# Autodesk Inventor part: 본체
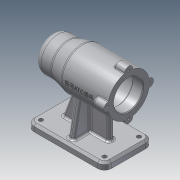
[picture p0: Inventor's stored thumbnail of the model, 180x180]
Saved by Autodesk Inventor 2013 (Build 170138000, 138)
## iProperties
Created: 2019-07
Part Number: 본체
Material: 알루미늄 6061
Document SubType Name: Modeling
Designer: 12
Density: 2.71 g/cm^3
Mass: 646.085 g
Surface Area: 655.731 cm^2
Volume: 238.408 cm^3
Author: 12
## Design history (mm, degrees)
sketch "스케치1"
  geometry: L1 (-56, 0)-(56, 0); L2 (-56, 0)-(-56, 25); L3 (-56, 25)-(-31, 25); L4 (-31, 25)-(-11, 30); L5 (-11, 30)-(56, 30); L6 (56, 30)-(56, 0); 2 further points
  constraints: 12 end point, 2 parallel, 2 perpendicular, 1 coincident, 1 horizontal, 1 midpoint
  dimensions: "d0" = 112 distance of L1.start L1.end; "d1" = 60 diameter of L5 L1; "d2" = 50 diameter of L3 L1; "d3" = 45 distance from line of L4.end L2; "d4" = 25 distance of L2.end L3.end
revolve "회전1" sketch "스케치1" stored, may be unused: angle "d5" = 90 deg
sketch "스케치2"
  geometry: C1 r 30 at (0, 0) reference; C2 r 21 at (0, 0)
  constraints: 1 centre point, 1 coincident
  dimensions: "d6" = 42 diameter of C2
extrude "돌출1" cut sketch "스케치2" distance "d7" = 15; taper "d8" = 0 deg
sketch "스케치3"
  geometry: C1 r 21 at (0, 0) reference; C2 r 24 at (0, 0)
  constraints: 1 centre point, 1 coincident
  dimensions: "d9" = 48 diameter of C2
extrude "돌출2" cut sketch "스케치3" distance "d10" = 54; taper "d11" = 0 deg
sketch "스케치4"
  geometry: C1 r 24 at (0, 0) reference; C2 r 21 at (0, 0)
  constraints: 1 centre point, 1 coincident
  dimensions: "d12" = 42 diameter of C2
extrude "돌출3" cut sketch "스케치4" distance "d13" = 12; taper "d14" = 0 deg
sketch "스케치5"
  geometry: C1 r 21 at (0, 0) reference; C2 r 17.5 at (0, 0)
  constraints: 1 centre point, 1 coincident
  dimensions: "d15" = 35 diameter of C2
extrude "돌출4" cut sketch "스케치5" distance "d16" = 18; taper "d17" = 0 deg
sketch "스케치6"
  geometry: C1 r 17.5 at (0, 0) reference; C2 r 16 at (0, 0)
  constraints: 1 centre point, 1 coincident
  dimensions: "d18" = 32 diameter of C2
extrude "돌출5" cut sketch "스케치6" distance "d19" = 4; taper "d20" = 0 deg
sketch "스케치8"
  geometry: L1 (0, 0)-(0, 30); C1 r 30 at (0, 0) reference; C2 r 6 at (0, 30)
  constraints: 2 end point, 1 centre point, 1 coincident, 1 vertical
  dimensions: "d26" = 30 distance of L1.start L1.end; "d27" = 12 diameter of C2
extrude "돌출6" join sketch "스케치8" distance "d28" = 16; taper "d29" = 0 deg
sketch "스케치9"
  geometry: A1 r 6 centre (0, 0) between (5.97, -0.6) and (-5.97, -0.6) reference; A2 r 6 centre (-30, -30) between (-29.4, -24.03) and (-29.4, -35.97) reference; A3 r 6 centre (0, -60) between (-5.97, -59.4) and (5.97, -59.4) reference; A4 r 6 centre (30, -30) between (29.4, -35.97) and (29.4, -24.03) reference; 4 further points
  constraints: 4 coincident
hole "구멍1" sketch "스케치9" at (0, 0), (30, -30), (-30, -30), (0, -60) diameter "d33" = 3.242; stored, may be unused: countersink angle "d37" = 90 deg, drill point angle "d39" = 118 deg; dims "d34" = 8, "d35" = 4, "d36" = 2, "d38" = 11
sketch "스케치10"
  geometry: C1 r 16 at (0, 0) reference; C2 r 10.5 at (0, 0)
  constraints: 1 centre point, 1 coincident
  dimensions: "d41" = 21 diameter of C2
extrude "돌출7" cut sketch "스케치10" distance "d42" = 3; taper "d43" = 0 deg
node "작업 평면1"
sketch "스케치11"
  geometry: L1 (56, 35)-(-56, 35); L2 (-56, 35)-(-56, -35); L3 (-56, -35)-(56, -35); L4 (56, -35)-(56, 35); L5 (56, 5.97)-(56, 29.4) reference; L6 (56, 6)-(56, -6) reference; L7 (56, -29.4)-(56, -5.97) reference; L8 (56, -29.4)-(56, -36) reference; L9 (56, 36)-(56, 29.4) reference; 2 further points
  constraints: 8 end point, 2 midpoint, 2 parallel, 1 horizontal, 1 perpendicular
  dimensions: "d45" = 112 distance of L3.end L2.end; "d46" = 70 distance of L2.end L1.end
extrude "돌출8" join sketch "스케치11" distance "d47" = 10; taper "d48" = 0 deg
fillet "모깎기1" dims "d60" = 10
sketch "스케치14"
  geometry: A1 r 10 centre (-46, 25) between (-46, 35) and (-56, 25) reference; A2 r 10 centre (-46, -25) between (-56, -25) and (-46, -35) reference; A3 r 10 centre (46, -25) between (46, -35) and (56, -25) reference; A4 r 10 centre (46, 25) between (56, 25) and (46, 35) reference; 5 further points
  constraints: 4 coincident
hole "구멍2" sketch "스케치14" at (-46, 25), (46, 25), (-46, -25), (46, -25) diameter "d61" = 6; stored, may be unused: countersink angle "d65" = 90 deg, drill point angle "d67" = 118 deg; dims "d62" = 8, "d63" = 4, "d64" = 2, "d66" = 11
fillet "모깎기2" dims "d68" = 10
fillet "모깎기3" dims "d69" = 0.3
fillet "모깎기4" dims "d70" = 3
fillet "모깎기5" dims "d71" = 3
chamfer "모따기1" distance "d72" = 1; stored, may be unused: second distance "d73" = 2, angle "d74" = 45 deg
chamfer "모따기2" distance "d75" = 3; stored, may be unused: second distance "d76" = 2, angle "d77" = 45 deg
sketch "스케치20"
  geometry: L1 (3, 4)-(31, 4); L2 (31, 4)-(31, -4); L3 (31, -4)-(3, -4); L4 (3, -4)-(3, 4); L5 (56, -25)-(56, 25) reference; L6 (46, -32)-(-46, -32) reference; L7 (46, 35)-(-46, 35) reference; L8 (-46, -35)-(46, -35) reference; 1 further point
  constraints: 8 end point, 2 parallel, 1 horizontal, 1 perpendicular
  dimensions: "d103" = 25 distance between parallel lines of L5 L2; "d119" = 28 distance of L1.start L1.end; "d120" = 31 distance between parallel lines of L7 L1; "d121" = 28 distance between parallel lines of L6 L3
extrude "돌출12" join sketch "스케치20" stored distance "d104" = 8; taper "d105" = 0 deg
fillet "모깎기6" dims "d78" = 3
fillet "모깎기7" dims "d79" = 3
fillet "모깎기8" dims "d80" = 1
node "작업 평면2"
sketch "스케치16"
  geometry: L1 (56, 6.771)-(56, 29.226) reference; L2 (56, 36)-(56, 30.171) reference; 2 further points
  constraints: 1 horizontal alignment, 1 other
  dimensions: "d85" = 42 distance from line of L2 point (14, 0)
feature "엠보싱1" sketch "스케치16" dims "d0" = 112, "d1" = 60, "d2" = 50, "d3" = 45, "d4" = 25, "d10" = 54, "d86" = 0.5, "d87" = 0
sketch "스케치17"
  geometry: L1 (45, -28.379)-(44.026, -30) reference; L2 (44.026, -30)-(45, -31.621) reference; L3 (45, -31.621)-(56, -31.621) reference; L4 (56, -31.621)-(56, -36) reference; L5 (56, -36)-(43, -36) reference; L6 (40, -33)-(40, -31) reference; L7 (39, -30)-(31, -30) reference; L8 (31, -70)-(53, -70) reference; L9 (53, -70)-(56, -73) reference; L10 (56, -73)-(56, -80) reference; L11 (56, -80)-(-56, -80) reference; L12 (-56, -80)-(-56, -73) reference; L13 (-56, -73)-(-53, -70) reference; L14 (-53, -70)-(3, -70) reference; L15 (3, -30)-(-11, -30) reference; L16 (-11, -30)-(-31, -25) reference; L17 (-31, -25)-(-46, -25) reference; L18 (-56, -15)-(-56, 15) reference; L19 (-46, 25)-(-31, 25) reference; L20 (-31, 25)-(-11, 30) reference; L21 (-11, 30)-(39, 30) reference; L22 (40, 31)-(40, 33) reference; L23 (43, 36)-(56, 36) reference; L24 (56, 36)-(56, 31.621) reference; L25 (56, 31.621)-(45, 31.621) reference; L26 (45, 31.621)-(44.026, 30) reference; L27 (44.026, 30)-(45, 28.379) reference; L28 (45, 28.379)-(56, 28.379) reference; L29 (56, 28.379)-(56, 22) reference; L30 (56, 22)-(55, 21) reference; L31 (55, 21)-(41, 21) reference; L32 (38, 24)-(-10, 24) reference; L33 (-13, 21)-(-24.7, 21) reference; L34 (-25, 20.7)-(-25, 17.5) reference; L35 (-25, 17.5)-(-42.7, 17.5) reference; L36 (-43, 17.2)-(-43, 16) reference; L37 (-43, 16)-(-46.7, 16) reference; L38 (-47, 15.7)-(-47, 10.5) reference; L39 (-50, 7.5)-(-50, -7.5) reference; L40 (-47, -10.5)-(-47, -15.7) reference; L41 (-46.7, -16)-(-43, -16) reference; L42 (-43, -16)-(-43, -17.2) reference; L43 (-42.7, -17.5)-(-25, -17.5) reference; L44 (-25, -17.5)-(-25, -20.7) reference; L45 (-24.7, -21)-(-13, -21) reference; L46 (-10, -24)-(38, -24) reference; L47 (41, -21)-(55, -21) reference; L48 (55, -21)-(56, -22) reference; L49 (56, -22)-(56, -28.379) reference; L50 (56, -28.379)-(45, -28.379) reference; L51 (-20.57, -27.607)-(-36, -70); L52 (31, -30)-(31, -70) reference; L53 (3, -70)-(3, -30) reference; A1 r 3 centre (43, -33) between (40, -33) and (43, -36) reference; A2 r 1 centre (39, -31) between (40, -31) and (39, -30) reference; A3 r 10 centre (-46, -15) between (-56, -15) and (-46, -25) reference; A4 r 10 centre (-46, 15) between (-46, 25) and (-56, 15) reference; A5 r 1 centre (39, 31) between (39, 30) and (40, 31) reference; A6 r 3 centre (43, 33) between (43, 36) and (40, 33) reference; A7 r 3 centre (38, 21) between (41, 21) and (38, 24) reference; A8 r 3 centre (-10, 21) between (-10, 24) and (-13, 21) reference; A9 r 0.3 centre (-24.7, 20.7) between (-24.7, 21) and (-25, 20.7) reference; A10 r 0.3 centre (-42.7, 17.2) between (-42.7, 17.5) and (-43, 17.2) reference; A11 r 0.3 centre (-46.7, 15.7) between (-46.7, 16) and (-47, 15.7) reference; A12 r 3 centre (-47, 7.5) between (-47, 10.5) and (-50, 7.5) reference; A13 r 3 centre (-47, -7.5) between (-50, -7.5) and (-47, -10.5) reference; A14 r 0.3 centre (-46.7, -15.7) between (-47, -15.7) and (-46.7, -16) reference; A15 r 0.3 centre (-42.7, -17.2) between (-43, -17.2) and (-42.7, -17.5) reference; A16 r 0.3 centre (-24.7, -20.7) between (-25, -20.7) and (-24.7, -21) reference; A17 r 3 centre (-10, -21) between (-13, -21) and (-10, -24) reference; A18 r 3 centre (38, -21) between (38, -24) and (41, -21) reference; 1 further point
  constraints: 2 end point, 2 point on line
  dimensions: "d88" = 110 deg angle of L14 L51; "d89" = 20 distance from line of L12 L51.end
feature "리브1" sketch "스케치17" dims "d90" = 1, "d91" = 8, "d92" = 0, "d93" = 0, "d94" = 1, "d95" = 1
sketch "스케치21"
  geometry: L1 (-70, 32)-(-70, 4) reference; L2 (-70, 4)-(-29.732, 4) reference; L3 (0.254, 29.999)-(0.254, 30.499) reference; L4 (0.648, 30.493)-(0.648, 29.993) reference; L5 (-29.732, -4)-(-70, -4) reference; L6 (-70, -4)-(-70, -32) reference; L7 (-70, -32)-(-73, -35) reference; L8 (-73, -35)-(-80, -35) reference; L9 (-80, -35)-(-80, 35) reference; L10 (-80, 35)-(-73, 35) reference; L11 (-73, 35)-(-70, 32) reference; L12 (-22.666, 19.654)-(-70, 28); C1 r 24 at (0, 0) reference; A1 r 30 centre (0, 0) between (0.254, 29.999) and (-29.732, 4) reference; A2 r 30.5 centre (0, 0) between (0.648, 30.493) and (0.254, 30.499) reference; A3 r 30 centre (0, 0) between (-29.732, -4) and (0.648, 29.993) reference; 1 further point
  constraints: 2 end point, 1 point on circle, 1 point on line
  dimensions: "d106" = 7 distance from line of L10 L12.end; "d107" = 100 deg angle of L1 L12
feature "리브2" sketch "스케치21" dims "d108" = 1, "d109" = 8, "d110" = 0, "d111" = 0, "d112" = 1, "d113" = 1
fillet "모깎기14" dims "d114" = 3
fillet "모깎기15" dims "d115" = 3
chamfer "모따기3" distance "d116" = 1; stored, may be unused: second distance "d117" = 2, angle "d118" = 45 deg
node "솔리드1"
pattern_circular "원형 패턴1" dims angle "d31" = 360 deg
mirror "대칭1"
node "절단 모서리 투영4"
node "절단 모서리 투영7"
